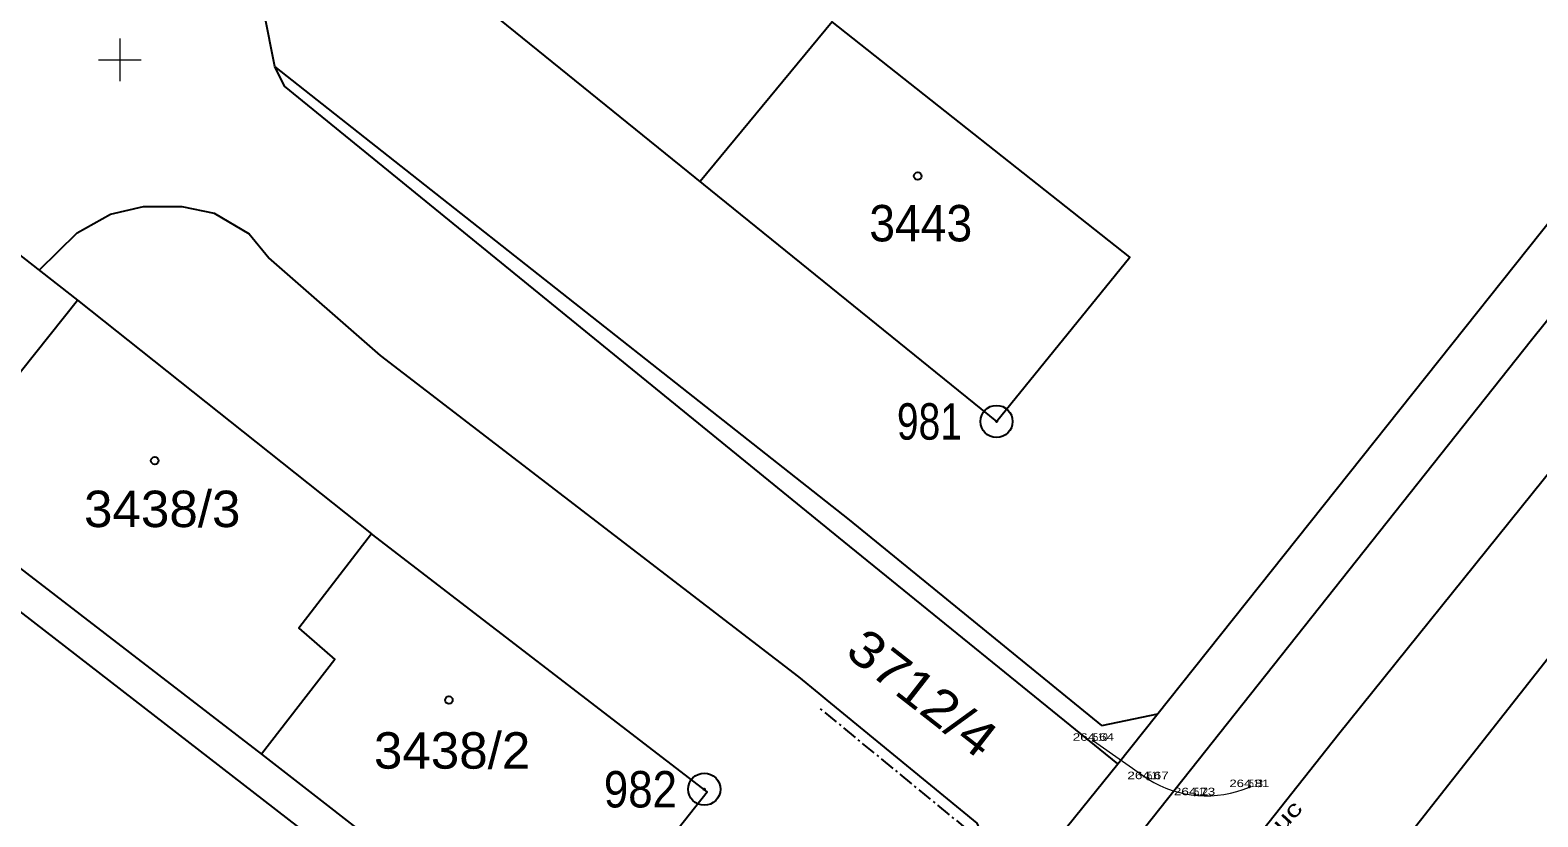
# Model space of a CAD drawing. Extents: x -568530 to -568223, y -1154101 to -1153740.
# Drawn here: x -568404.2 to -568333.8, y -1153835.3 to -1153798.6 of the extents above; entities that cross this region are included whole.
import ezdxf
from ezdxf.enums import TextEntityAlignment as Align

# ---------------------------------------------------------------- set-up
doc = ezdxf.new("R2010")
doc.units = 0
doc.header["$LTSCALE"] = 0.14
doc.header["$PDMODE"] = 32
doc.header["$PDSIZE"] = 0.07
doc.linetypes.add('DOT_DASHED', pattern=[7.7, 5, -1.2, 0.3, -1.2])
for name, color, linetype, lineweight in [('1', 7, 'Continuous', 25), ('10', 7, 'Continuous', 13), ('11', 7, 'Continuous', 13), ('12', 7, 'Continuous', 13), ('17', 7, 'Continuous', 13), ('25', 7, 'Continuous', 13), ('4', 7, 'Continuous', 25), ('42', 7, 'Continuous', 13), ('6', 7, 'DOT_DASHED', 25), ('61', 7, 'Continuous', 13)]:
    doc.layers.add(name, color=color, linetype=linetype, lineweight=lineweight)
for name, color, linetype in [('13', 7, 'Continuous'), ('18', 7, 'Continuous'), ('19', 7, 'Continuous')]:
    doc.layers.add(name, color=color, linetype=linetype)

msp = doc.modelspace()

# ---------------------------------------------------------------- linework, layer by layer
at = {"layer": '1'}
msp.add_line((-568405.4, -1153808.54), (-568401.97, -1153811.21), dxfattribs=at)
for points in [[(-568353.42, -1153832.84), (-568324.07, -1153795.96), (-568298.53, -1153763.68), (-568279.81, -1153739.94)], [(-568412.56, -1153907.8), (-568411.98, -1153907.12), (-568411.65, -1153906.73), (-568402.04, -1153895.41), (-568393.94, -1153886.59), (-568382.28, -1153873.78), (-568334.11, -1153813.06), (-568281.93, -1153748.16)], [(-568386.84, -1153794.41), (-568359.08, -1153816.87), (-568352.86, -1153809.2), (-568366.76, -1153798.23), (-568372.92, -1153805.67)], [(-568359.48, -1153840.35), (-568353.42, -1153832.84), (-568366.2, -1153822.48), (-568392.31, -1153801.22), (-568392.76, -1153800.31), (-568393.76, -1153795.28)], [(-568403.77, -1153809.81), (-568401.99, -1153808.07), (-568400.44, -1153807.2), (-568398.89, -1153806.84), (-568397.11, -1153806.84), (-568395.6, -1153807.16), (-568393.97, -1153808.11), (-568393.04, -1153809.23)], [(-568383.87, -1153867.96), (-568379, -1153861.51), (-568379.35, -1153865.15), (-568369.44, -1153852.85), (-568368.51, -1153851.61), (-568359.48, -1153840.35), (-568358.98, -1153837.93), (-568359.22, -1153837.4), (-568359.99, -1153835.62), (-568366.98, -1153829.88), (-568367.36, -1153829.57), (-568368.31, -1153828.79), (-568387.83, -1153813.79), (-568393.04, -1153809.23)], [(-568407.36, -1153816.47), (-568406.61, -1153817.02), (-568401.97, -1153811.21), (-568388.26, -1153822.12)], [(-568408.11, -1153818.94), (-568409.17, -1153820.25), (-568393.38, -1153832.39)]]:
    msp.add_lwpolyline(points, dxfattribs=at)
msp.add_lwpolyline([(-568379.65, -1153843.07), (-568372.58, -1153834.15), (-568388.26, -1153822.12), (-568391.64, -1153826.52), (-568389.96, -1153827.98), (-568393.38, -1153832.39)], close=True, dxfattribs=at)
at = {"layer": '10'}
msp.add_line((-568354.56, -1153831.77), (-568352.01, -1153833.56), dxfattribs=at)
msp.add_arc((-568349.2898, -1153829.2037), 5.1358, 238.01773, 293.03667, dxfattribs=at)
at = {"layer": '11'}
for p in [(-568354.56, -1153831.77), (-568352.01, -1153833.56), (-568347.28, -1153833.93), (-568349.84, -1153834.31)]:
    msp.add_point(p, dxfattribs=at)
at = {"layer": '25', "lineweight": 25}
for centre, radius in [((-568362.76, -1153805.42), 0.175), ((-568359.08, -1153816.87), 0.75), ((-568359.08, -1153816.87), 0.032), ((-568398.37, -1153818.7), 0.175), ((-568384.64, -1153829.87), 0.175), ((-568372.72, -1153834.03), 0.75), ((-568372.72, -1153834.03), 0.032)]:
    msp.add_circle(centre, radius, dxfattribs=at)
at = {"layer": '4'}
msp.add_line((-568354.16, -1153831.06), (-568351.56, -1153830.51), dxfattribs=at)
for points in [[(-568271.05, -1153741.89), (-568310.68, -1153791.16), (-568343.12, -1153831.47), (-568381.67, -1153880.2), (-568407.5, -1153911.44)], [(-568401.59, -1153914.63), (-568397.99, -1153910.05), (-568332.4, -1153826.72), (-568306.48, -1153794.28), (-568270.78, -1153751.53)], [(-568354.16, -1153831.06), (-568365.94, -1153821.46), (-568392.76, -1153800.31)], [(-568369.44, -1153852.85), (-568378.94, -1153845.64), (-568379.34, -1153845.34), (-568413.29, -1153819.07)]]:
    msp.add_lwpolyline(points, dxfattribs=at)
at = {"layer": '6'}
msp.add_line((-568360.4, -1153835.94), (-568367.3, -1153830.27), dxfattribs=at)
at = {"layer": '61'}
for p, q in [((-568400, -1153799), (-568400, -1153801)), ((-568401, -1153800), (-568399, -1153800))]:
    msp.add_line(p, q, dxfattribs=at)

# ---------------------------------------------------------------- texts
at = {"layer": '12'}
for s, width, p in [('264.64', 1.35, (-568354.56, -1153831.77)), ('264.67', 1.35, (-568352.01, -1153833.56)), ('264.73', 1.35, (-568349.84, -1153834.31)), ('264.81', 1.3, (-568347.28, -1153833.93))]:
    msp.add_text(s, height=0.35, dxfattribs=dict(at, width=width)).set_placement(p, align=Align.CENTER)
at = {"layer": '13'}
for s, width, p in [('510', 0.85, (-568354.56, -1153831.77)), ('511', 0.7, (-568352.01, -1153833.56)), ('512', 0.8, (-568349.84, -1153834.31)), ('513', 0.8, (-568347.28, -1153833.93))]:
    msp.add_text(s, height=0.35, dxfattribs=dict(at, width=width)).set_placement(p)
at = {"layer": '17'}
for s, width, p in [('981', 0.8, (-568360.696, -1153817.72)), ('982', 0.9, (-568373.995, -1153834.88))]:
    msp.add_text(s, height=1.7, dxfattribs=dict(at, width=width)).set_placement(p, align=Align.RIGHT)
at = {"layer": '18', "width": 1.15}
msp.add_text('3712/4', height=1.7, rotation=322.003, dxfattribs=at).set_placement((-568366.21, -1153827.746))
at = {"layer": '19'}
for s, width, p in [('3443', 0.95, (-568365.02, -1153808.47)), ('3438/3', 1.05, (-568401.67, -1153821.8)), ('3438/2', 1.05, (-568388.14, -1153833.07))]:
    msp.add_text(s, height=1.7, dxfattribs=dict(at, width=width)).set_placement(p)
at = {"layer": '42', "width": 1.4}
msp.add_text('smer Olomouc', height=0.75, rotation=47.66, dxfattribs=at).set_placement((-568347.8222, -1153838.3476), align=Align.CENTER)

doc.saveas('drawing.dxf')
